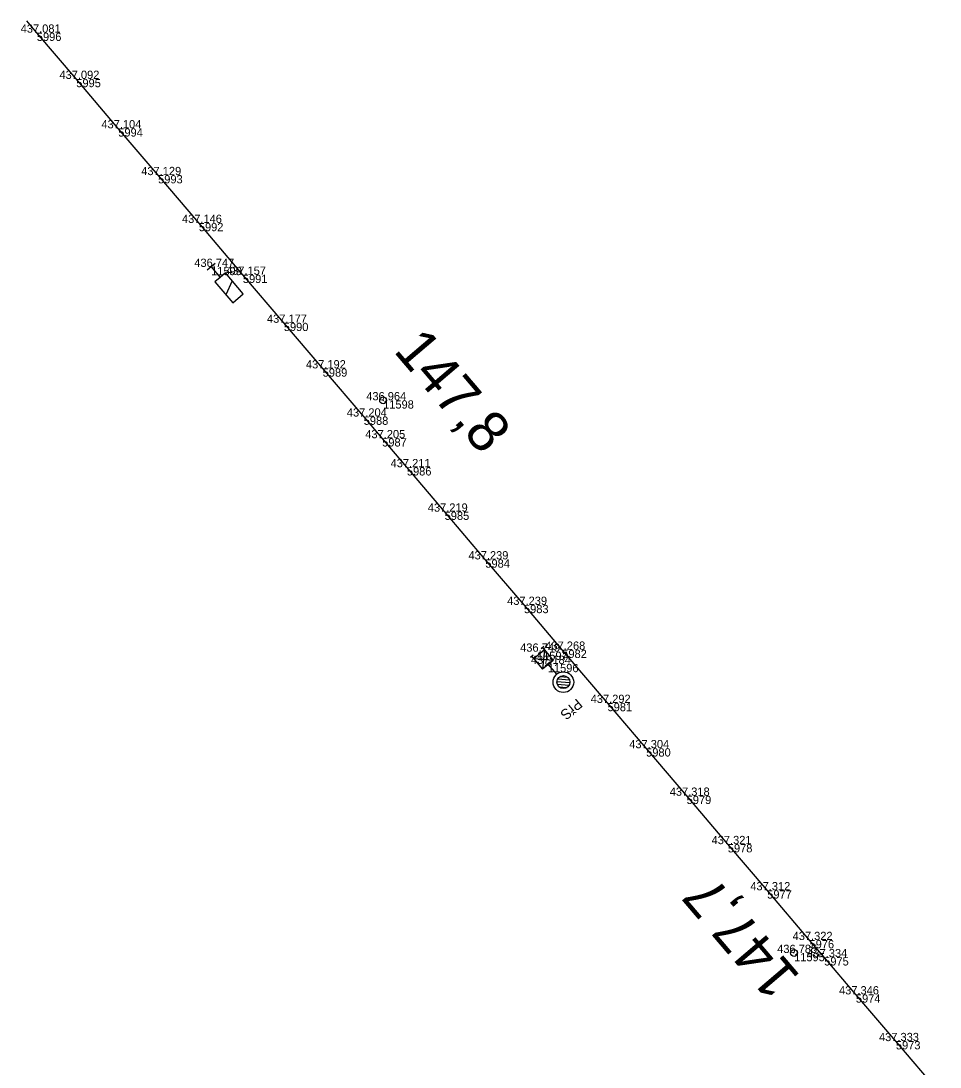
# Model space of a CAD drawing. Extents: x -654154 to -652650, y -1166925 to -1164904.
# Drawn here: x -654154.2 to -654020.7, y -1165056.1 to -1164904.1 of the extents above; entities that cross this region are included whole.
import ezdxf

# ---------------------------------------------------------------- set-up
doc = ezdxf.new("R2010")
doc.units = 0
for name, color, linetype in [('Vrstva 1', 7, 'Continuous'), ('Vrstva 6', 7, 'Continuous'), ('Vrstva 60', 7, 'Continuous'), ('Vrstva 61', 7, 'Continuous'), ('Vrstva 7', 7, 'Continuous')]:
    doc.layers.add(name, color=color, linetype=linetype)

msp = doc.modelspace()

# ---------------------------------------------------------------- linework, layer by layer
at = {"layer": 'Vrstva 1'}
for points in [[(-654140.08, -1164919.71), (-654146.18, -1164912.53), (-654151.91, -1164905.81), (-654153.36, -1164904.1)], [(-654020.66, -1165059.91), (-654027.08, -1165052.37), (-654032.89, -1165045.58), (-654037.5, -1165040.18), (-654039.63, -1165037.68), (-654045.78, -1165030.45), (-654051.5, -1165023.74), (-654057.48, -1165016.71), (-654063.37, -1165009.8), (-654068.98, -1165003.22), (-654075.56, -1164995.49), (-654081.12, -1164988.97), (-654086.74, -1164982.36), (-654092.65, -1164975.42), (-654098.14, -1164968.96), (-654101.73, -1164964.75), (-654104.41, -1164961.6), (-654110.37, -1164954.6), (-654116.02, -1164947.97), (-654121.97, -1164940.99), (-654128.37, -1164933.46), (-654134.29, -1164926.51), (-654140.08, -1164919.71)]]:
    msp.add_lwpolyline(points, dxfattribs=at)
at = {"layer": 'Vrstva 6'}
for p, q in [((-654077.28, -1164997.23), (-654078.04, -1164997.87)), ((-654076.37, -1164999.06), (-654077.66, -1164997.55)), ((-654076.34, -1165000.1), (-654074.46, -1165000.25)), ((-654076.3, -1165000.48), (-654074.55, -1165000.62)), ((-654076.22, -1164999.73), (-654074.51, -1164999.87)), ((-654075.89, -1164999.38), (-654074.79, -1164999.47)), ((-654076.05, -1165000.88), (-654074.86, -1165000.97))]:
    msp.add_line(p, q, dxfattribs=at)
for centre, radius in [((-654075.4, -1165000.2), 1.5), ((-654075.4, -1165000.19), 0.949)]:
    msp.add_circle(centre, radius, dxfattribs=at)
at = {"layer": 'Vrstva 60'}
for p, q in [((-654151.91, -1164905.81), (-654151.91, -1164905.81)), ((-654146.18, -1164912.53), (-654146.18, -1164912.53)), ((-654140.08, -1164919.71), (-654140.08, -1164919.71)), ((-654134.29, -1164926.51), (-654134.29, -1164926.51)), ((-654128.37, -1164933.46), (-654128.37, -1164933.46)), ((-654126.58, -1164939.85), (-654126.58, -1164939.85)), ((-654121.97, -1164940.99), (-654121.97, -1164940.99)), ((-654116.02, -1164947.97), (-654116.02, -1164947.97)), ((-654110.37, -1164954.6), (-654110.37, -1164954.6)), ((-654101.59, -1164959.24), (-654101.59, -1164959.24)), ((-654104.41, -1164961.6), (-654104.41, -1164961.6)), ((-654101.73, -1164964.75), (-654101.73, -1164964.75)), ((-654098.14, -1164968.96), (-654098.14, -1164968.96)), ((-654092.65, -1164975.42), (-654092.65, -1164975.42)), ((-654086.74, -1164982.36), (-654086.74, -1164982.36)), ((-654081.12, -1164988.97), (-654081.12, -1164988.97)), ((-654079.23, -1164995.77), (-654079.23, -1164995.77)), ((-654075.56, -1164995.49), (-654075.56, -1164995.49)), ((-654077.66, -1164997.55), (-654077.66, -1164997.55)), ((-654068.98, -1165003.22), (-654068.98, -1165003.22)), ((-654063.37, -1165009.8), (-654063.37, -1165009.8)), ((-654057.48, -1165016.71), (-654057.48, -1165016.71)), ((-654051.5, -1165023.74), (-654051.5, -1165023.74)), ((-654045.78, -1165030.45), (-654045.78, -1165030.45)), ((-654039.63, -1165037.68), (-654039.63, -1165037.68)), ((-654041.87, -1165039.56), (-654041.87, -1165039.56)), ((-654037.5, -1165040.18), (-654037.5, -1165040.18)), ((-654032.89, -1165045.58), (-654032.89, -1165045.58)), ((-654027.08, -1165052.37), (-654027.08, -1165052.37))]:
    msp.add_line(p, q, dxfattribs=at)
at = {"layer": 'Vrstva 7'}
for p, q in [((-654126.01, -1164939.37), (-654127.15, -1164940.34)), ((-654123.55, -1164941.87), (-654124.43, -1164943.93)), ((-654101.62, -1164959.2), (-654101.56, -1164959.28)), ((-654078.14, -1164995.52), (-654079.68, -1164996.79)), ((-654078.65, -1164995.29), (-654078.26, -1164994.97)), ((-654078.14, -1164995.52), (-654078.45, -1164995.13)), ((-654078.14, -1164995.52), (-654078.42, -1164998.33)), ((-654078.14, -1164995.52), (-654076.87, -1164997.07)), ((-654080.19, -1164996.56), (-654079.81, -1164996.24)), ((-654079.68, -1164996.79), (-654080, -1164996.4)), ((-654079.68, -1164996.79), (-654078.42, -1164998.33)), ((-654076.87, -1164997.07), (-654079.68, -1164996.79)), ((-654076.87, -1164997.07), (-654078.42, -1164998.33)), ((-654041.84, -1165039.59), (-654041.9, -1165039.52))]:
    msp.add_line(p, q, dxfattribs=at)
msp.add_lwpolyline([(-654126.58, -1164939.85), (-654125.28, -1164941.38), (-654126.05, -1164942.02), (-654123.45, -1164945.07), (-654121.93, -1164943.77), (-654124.52, -1164940.73), (-654125.28, -1164941.38)], dxfattribs=at)
for centre in [(-654101.59, -1164959.24), (-654041.87, -1165039.56)]:
    msp.add_circle(centre, 0.5, dxfattribs=at)

# ---------------------------------------------------------------- texts
at = {"layer": 'Vrstva 6'}
msp.add_text('PřS', height=1.5, rotation=220.4091, dxfattribs=at).set_placement((-654073.44, -1165002.5))
at = {"layer": 'Vrstva 60'}
for s, p in [('5996', (-654151.91, -1164907.01)), ('5995', (-654146.18, -1164913.73)), ('5994', (-654140.08, -1164920.91)), ('5993', (-654134.29, -1164927.71)), ('5992', (-654128.37, -1164934.66)), ('11599', (-654126.58, -1164941.05)), ('5991', (-654121.97, -1164942.19)), ('5990', (-654116.02, -1164949.17)), ('5989', (-654110.37, -1164955.8)), ('11598', (-654101.59, -1164960.44)), ('5988', (-654104.41, -1164962.8)), ('5987', (-654101.73, -1164965.95)), ('5986', (-654098.14, -1164970.16)), ('5985', (-654092.65, -1164976.62)), ('5984', (-654086.74, -1164983.56)), ('5983', (-654081.12, -1164990.17)), ('11597', (-654079.23, -1164996.97)), ('5982', (-654075.56, -1164996.69)), ('11596', (-654077.66, -1164998.75)), ('5981', (-654068.98, -1165004.42)), ('5980', (-654063.37, -1165011.01)), ('5979', (-654057.48, -1165017.91)), ('5978', (-654051.5, -1165024.94)), ('5977', (-654045.78, -1165031.65)), ('5976', (-654039.63, -1165038.88)), ('11595', (-654041.87, -1165040.76)), ('5975', (-654037.5, -1165041.38)), ('5974', (-654032.89, -1165046.78)), ('5973', (-654027.08, -1165053.57))]:
    msp.add_text(s, height=1.2, dxfattribs=at).set_placement(p)
at = {"layer": 'Vrstva 61'}
for s, p in [('437.081', (-654154.26, -1164905.81)), ('437.092', (-654148.63, -1164912.53)), ('437.104', (-654142.53, -1164919.71)), ('437.129', (-654136.74, -1164926.51)), ('437.146', (-654130.82, -1164933.46)), ('436.747', (-654129.03, -1164939.85)), ('437.157', (-654124.42, -1164940.99)), ('437.177', (-654118.47, -1164947.97)), ('437.192', (-654112.81, -1164954.6)), ('436.964', (-654104.04, -1164959.24)), ('437.204', (-654106.86, -1164961.6)), ('437.205', (-654104.18, -1164964.75)), ('437.211', (-654100.5, -1164968.96)), ('437.219', (-654095.1, -1164975.42)), ('437.239', (-654089.19, -1164982.36)), ('437.239', (-654083.57, -1164988.97)), ('437.268', (-654078.02, -1164995.49)), ('436.749', (-654081.68, -1164995.77)), ('437.184', (-654080.11, -1164997.55)), ('437.292', (-654071.43, -1165003.22)), ('437.304', (-654065.82, -1165009.8)), ('437.318', (-654059.94, -1165016.71)), ('437.321', (-654053.86, -1165023.74)), ('437.312', (-654048.23, -1165030.45)), ('437.322', (-654042.08, -1165037.68)), ('436.785', (-654044.33, -1165039.56)), ('437.334', (-654039.95, -1165040.18)), ('437.346', (-654035.34, -1165045.58)), ('437.333', (-654029.53, -1165052.37))]:
    msp.add_text(s, height=1.2, dxfattribs=at).set_placement(p)
at = {"layer": 'Vrstva 7'}
for s, rotation, p in [('147,8', 310.4208, (-654100.2, -1164952.08)), ('147,7', 130.4384, (-654040.82, -1165043))]:
    msp.add_text(s, height=6, rotation=rotation, dxfattribs=at).set_placement(p)

doc.saveas('drawing.dxf')
